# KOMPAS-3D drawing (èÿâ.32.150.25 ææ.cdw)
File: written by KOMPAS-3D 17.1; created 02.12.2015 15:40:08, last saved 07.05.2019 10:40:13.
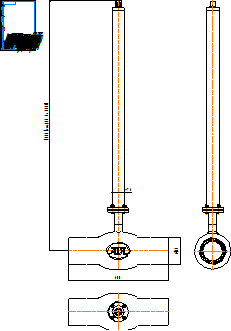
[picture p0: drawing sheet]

Sheet 1: A4, portrait

Title block, sheet 1: name: КШГ.32.150.25 СС; material: Внимание! Данный продукт является объектом авторского права ООО «Торговый Дом АДЛ». / Запрещается изменение, копирование, распространение / (в том числе путем копирования на другие сайты и ресурсы в Интернете) / или любое иное использование информации и объектов без предварительного / согласия правообладателя (ООО «Торговый Дом АДЛ»).; sheets: 1; organisation: ООО "Торговый дом АДЛ"; sheet format: A4; stored path: C:\Users\kka\KOMPAS_Work\Модели кранов для исследований\DN50\С удлинением\КШГ.32.050.40 СС ГЧ _ Шаровой кран БИВАЛ Ду50 Ру4 МПа редуцированный под приварку, с удлинением штока H=1100.cdw; drawn by: Климкович К.А.; drawn by, date: 07.12.16

Views: Вид 1, Проекционный вид 2
Referenced files in C:\Users\kka\KOMPAS_Work\Модели кранов для исследований\DN80\С удлинением\: КШТ.22.080.25 СС.a3d
Referenced files in C:\Users\kka\KOMPAS_Work\Модели кранов для исследований\DN150\С удлинением\: КШТ.22.150.25 СС.a3d, КШГ.35.125.25 СС Lстр600.a3d, КШГ.35.125.25 СС Lстр600.a3d!Деталь (локальная).m3d
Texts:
  Klimkovich
  ADL
  (от 480 до 5000)
Dimensions and other numbers on the sheet: 76; 1500; 600; 159; 1:1; 1; 07.12.16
